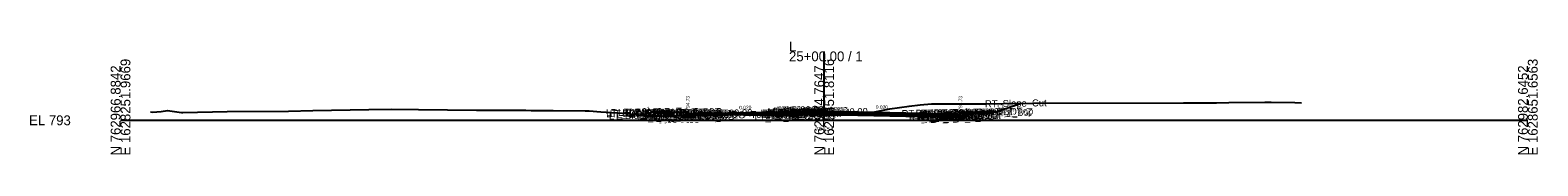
# Model space of a CAD drawing. Extents: x -26 to 4403, y -510 to 9556.
# Drawn here: x 974.3 to 1402.8, y 4990.3 to 5022.4 of the extents above; entities that cross this region are included whole.
import ezdxf

# ---------------------------------------------------------------- set-up
doc = ezdxf.new("R2010")
doc.units = 0
for name, color, linetype in [('Default', 7, 'Continuous'), ('Exist CMT Pavement', 7, 'Continuous'), ('Exist Cross Section Cell', 7, 'Continuous'), ('Exist XS Center Line Elevation Label', 7, 'Continuous'), ('Exist XS Ground Line', 7, 'Continuous'), ('Prop CMT Conc Surface', 7, 'Continuous'), ('Prop CMT Concrete Structures', 7, 'Continuous'), ('Prop CMT Pvmt Course 1', 7, 'Continuous'), ('Prop CMT Pvmt Course 1 CG', 7, 'Continuous'), ('Prop CMT Pvmt Course 1 Wedge', 7, 'Continuous'), ('Prop CMT Pvmt Course 2', 7, 'Continuous'), ('Prop CMT Pvmt Course 2 Wedge', 7, 'Continuous'), ('Prop CMT Pvmt Course 3', 7, 'Continuous'), ('Prop CMT Pvmt Course 3 Wedge', 7, 'Continuous'), ('Prop CMT Pvmt Surface', 7, 'Continuous'), ('Prop CMT Pvmt Wedge Surface 1', 7, 'Continuous'), ('Prop CMT Pvmt Wedge Surface 2', 7, 'Continuous'), ('Prop CMT Pvmt Wedge Surface 3', 7, 'Continuous'), ('Prop CMT Slope Grass', 7, 'Continuous'), ('Prop CMT Subgrade Earthwork', 7, 'Continuous'), ('Prop XS Hydro Elevations', 7, 'Continuous'), ('Prop XS SE Text', 7, 'Continuous'), ('Prop XS Side Slope Text', 7, 'Continuous'), ('Scratch_Level_0', 7, 'Continuous')]:
    doc.layers.add(name, color=color, linetype=linetype)

msp = doc.modelspace()

# ---------------------------------------------------------------- linework, layer by layer
at = {"layer": 'Exist CMT Pavement'}
msp.add_lwpolyline([(1163.26, 5001.5), (1165.91, 5001.58), (1171.22, 5001.76), (1177.05, 5001.59), (1190.76, 5001.23)], dxfattribs=at)
at = {"layer": 'Exist Cross Section Cell'}
for p, q in [((1200, 5000), (1200, 5019.58)), ((1000, 5000), (1200, 5000)), ((1200, 5000), (1400, 5000))]:
    msp.add_line(p, q, dxfattribs=at)
at = {"layer": 'Exist XS Ground Line'}
msp.add_lwpolyline([(1008.56, 5002.39), (1009.11, 5002.29), (1011.55, 5002.52), (1013.37, 5002.75), (1017.29, 5002.23), (1017.69, 5002.25), (1030.33, 5002.55), (1047.76, 5002.63), (1054.68, 5002.75), (1070.56, 5003.07), (1077.15, 5003.2), (1084.67, 5003.08), (1101.19, 5002.84), (1115.16, 5002.84), (1116.75, 5002.83), (1122.95, 5002.79), (1132.03, 5002.72), (1133.23, 5002.74), (1136.5, 5002.42), (1144.19, 5001.94), (1149.29, 5001.32), (1149.78, 5001.1), (1165.91, 5001.58), (1171.22, 5001.76), (1177.05, 5001.59), (1190.72, 5001.23), (1191.91, 5001.1), (1193.24, 5001.54), (1195.22, 5001.7), (1198.62, 5001.58), (1199.18, 5001.54), (1200, 5001.54), (1204.18, 5001.54), (1204.52, 5001.51), (1204.87, 5001.54), (1210.64, 5001.56), (1214.42, 5002.42), (1218.67, 5003.25), (1224.14, 5004.06), (1227.27, 5004.38), (1230.51, 5004.67), (1235.17, 5004.7), (1245.87, 5004.68), (1250.96, 5004.81), (1259.59, 5004.9), (1302.16, 5005.01), (1311.53, 5004.94), (1315.05, 5005.02), (1325.23, 5005.19), (1327.02, 5005.16), (1333.74, 5005.07), (1335.68, 5005)], dxfattribs=at)
at = {"layer": 'Prop CMT Conc Surface'}
for points in [[(1156.75, 5002.32), (1151.75, 5002.42)], [(1161.25, 5001.73), (1161.25, 5002.23), (1160.75, 5002.23)], [(1163.25, 5001.85), (1161.25, 5001.73)], [(1236.75, 5001.85), (1238.75, 5001.73)], [(1238.75, 5001.73), (1238.75, 5002.23), (1239.25, 5002.23)], [(1243.25, 5002.32), (1248.25, 5002.42)]]:
    msp.add_lwpolyline(points, dxfattribs=at)
at = {"layer": 'Prop CMT Concrete Structures'}
for points in [[(1151.75, 5002.09), (1151.75, 5002.42)], [(1151.75, 5002.42), (1156.75, 5002.32)], [(1156.75, 5001.99), (1151.75, 5002.09)], [(1156.75, 5002.32), (1156.75, 5001.99)], [(1163.25, 5001.85), (1161.25, 5001.73), (1161.25, 5002.23), (1160.75, 5002.23)], [(1160.75, 5002.23), (1160.75, 5001.22), (1163.25, 5001.27)], [(1163.25, 5001.27), (1163.25, 5001.85)], [(1196, 5002.67), (1195.99, 5002.83), (1195.24, 5003.08), (1194, 5003.11), (1192.76, 5002.84), (1192.01, 5002.59), (1192, 5002.43)], [(1192, 5002.43), (1196, 5002.67)], [(1236.75, 5001.85), (1238.75, 5001.73), (1238.75, 5002.23), (1239.25, 5002.23)], [(1239.25, 5002.23), (1239.25, 5001.22), (1236.75, 5001.27)], [(1236.75, 5001.27), (1236.75, 5001.85)], [(1248.25, 5002.42), (1243.25, 5002.32)], [(1243.25, 5002.32), (1243.25, 5001.99)], [(1243.25, 5001.99), (1248.25, 5002.09)], [(1248.25, 5002.09), (1248.25, 5002.42)]]:
    msp.add_lwpolyline(points, dxfattribs=at)
at = {"layer": 'Prop CMT Pvmt Course 1'}
for points in [[(1192, 5002.43), (1163.25, 5001.85)], [(1163.25, 5001.73), (1192, 5002.3)], [(1163.25, 5001.85), (1163.25, 5001.6), (1163.25, 5001.6), (1163.25, 5001.73)], [(1192, 5002.43), (1196, 5002.67)], [(1192, 5002.18), (1192, 5002.43)], [(1192, 5002.18), (1192, 5002.43)], [(1196, 5002.42), (1192, 5002.18)], [(1192, 5002.3), (1192, 5002.18), (1192, 5002.18)], [(1196, 5002.67), (1196, 5002.42)], [(1196, 5002.67), (1236.75, 5001.85)], [(1196, 5002.42), (1196, 5002.67)], [(1236.75, 5001.6), (1196, 5002.42)], [(1236.75, 5001.85), (1236.75, 5001.6)]]:
    msp.add_lwpolyline(points, dxfattribs=at)
msp.add_lwpolyline([(1196, 5002.42), (1196, 5002.54), (1196, 5002.54), (1196, 5002.42)], close=True, dxfattribs=at)
at = {"layer": 'Prop CMT Pvmt Course 1 CG'}
for points in [[(1163.25, 5001.27), (1160.25, 5001.21), (1159.91, 5000.87)], [(1163.25, 5000.94), (1163.25, 5001.27)], [(1236.75, 5001.27), (1239.75, 5001.21), (1240.09, 5000.87)], [(1236.75, 5000.94), (1236.75, 5001.27)], [(1159.91, 5000.87), (1163.25, 5000.94)], [(1240.09, 5000.87), (1236.75, 5000.94)]]:
    msp.add_lwpolyline(points, dxfattribs=at)
at = {"layer": 'Prop CMT Pvmt Course 1 Wedge'}
for points in [[(1163.25, 5001.73), (1165.91, 5001.78), (1171.22, 5001.89), (1171.27, 5001.89), (1177.05, 5002), (1190.72, 5002.28), (1191.66, 5002.3), (1191.91, 5002.3), (1192, 5002.3)], [(1192, 5002.18), (1191.91, 5002.18), (1191.66, 5002.17), (1190.72, 5002.15), (1177.05, 5001.88), (1171.27, 5001.76), (1171.22, 5001.76), (1165.91, 5001.66), (1163.25, 5001.6)], [(1163.25, 5001.6), (1163.25, 5001.73)], [(1192, 5002.3), (1192, 5002.18)]]:
    msp.add_lwpolyline(points, dxfattribs=at)
at = {"layer": 'Prop CMT Pvmt Course 2'}
for points in [[(1163.25, 5001.27), (1163.25, 5001.27), (1163.25, 5001.6), (1163.25, 5001.6)], [(1163.25, 5001.6), (1163.25, 5001.27)], [(1192, 5002.18), (1196, 5002.42)], [(1192, 5001.84), (1192, 5002.18)], [(1196, 5002.08), (1192, 5001.84)], [(1196, 5002.42), (1196, 5002.08)], [(1196, 5002.08), (1196, 5002.42)], [(1196, 5002.42), (1236.75, 5001.6)], [(1236.75, 5001.27), (1196, 5002.08)], [(1236.75, 5001.6), (1236.75, 5001.27)]]:
    msp.add_lwpolyline(points, dxfattribs=at)
at = {"layer": 'Prop CMT Pvmt Course 2 Wedge'}
for points in [[(1163.25, 5001.6), (1165.91, 5001.66), (1171.22, 5001.76), (1171.27, 5001.76), (1177.05, 5001.88), (1190.72, 5002.15), (1191.66, 5002.17), (1191.91, 5002.18), (1192, 5002.18)], [(1192, 5001.84), (1191.91, 5001.84), (1191.66, 5001.84), (1190.72, 5001.82), (1178.12, 5001.57), (1177.05, 5001.59), (1171.27, 5001.75), (1171.22, 5001.76), (1165.91, 5001.58), (1163.25, 5001.5)], [(1163.25, 5001.5), (1163.25, 5001.6)], [(1192, 5002.18), (1192, 5001.84)]]:
    msp.add_lwpolyline(points, dxfattribs=at)
at = {"layer": 'Prop CMT Pvmt Course 3'}
for points in [[(1163.25, 5001.27), (1163.25, 5001.27), (1163.25, 5000.94), (1163.25, 5000.94)], [(1163.25, 5000.94), (1163.25, 5001.27)], [(1192, 5001.84), (1196, 5002.08)], [(1192, 5001.51), (1192, 5001.84)], [(1196, 5001.75), (1192, 5001.51)], [(1196, 5002.08), (1196, 5001.75)], [(1196, 5002.08), (1236.75, 5001.27)], [(1196, 5001.75), (1196, 5002.08)], [(1236.75, 5000.94), (1196, 5001.75)], [(1236.75, 5001.27), (1236.75, 5000.94)]]:
    msp.add_lwpolyline(points, dxfattribs=at)
at = {"layer": 'Prop CMT Pvmt Course 3 Wedge'}
for points in [[(1178.12, 5001.57), (1190.72, 5001.82)], [(1192, 5001.14), (1191.91, 5001.1), (1191.66, 5001.12), (1190.72, 5001.23), (1178.12, 5001.57)], [(1190.72, 5001.82), (1191.66, 5001.84), (1191.91, 5001.84), (1192, 5001.84)]]:
    msp.add_lwpolyline(points, dxfattribs=at)
at = {"layer": 'Prop CMT Pvmt Surface'}
for points in [[(1192, 5002.43), (1163.25, 5001.85)], [(1192, 5002.43), (1196, 5002.67)], [(1196, 5002.67), (1236.75, 5001.85)]]:
    msp.add_lwpolyline(points, dxfattribs=at)
at = {"layer": 'Prop CMT Pvmt Wedge Surface 1'}
for points in [[(1192, 5002.3), (1163.25, 5001.73)], [(1163.25, 5001.6), (1163.25, 5001.85)], [(1163.25, 5001.73), (1163.25, 5001.6), (1163.25, 5001.6)], [(1192, 5002.43), (1192, 5002.18), (1192, 5002.18), (1192, 5002.3)]]:
    msp.add_lwpolyline(points, dxfattribs=at)
at = {"layer": 'Prop CMT Pvmt Wedge Surface 2'}
for points in [[(1192, 5002.18), (1163.25, 5001.6)], [(1163.25, 5001.6), (1163.25, 5001.85)], [(1192, 5002.43), (1192, 5002.18)]]:
    msp.add_lwpolyline(points, dxfattribs=at)
at = {"layer": 'Prop CMT Pvmt Wedge Surface 3'}
for points in [[(1163.25, 5001.27), (1163.25, 5001.85)], [(1192, 5001.84), (1163.25, 5001.27)], [(1192, 5002.43), (1192, 5001.84)]]:
    msp.add_lwpolyline(points, dxfattribs=at)
at = {"layer": 'Prop CMT Slope Grass'}
for points in [[(1160.75, 5002.23), (1151.25, 5002.42), (1148.31, 5001.44)], [(1239.25, 5002.23), (1248.25, 5002.41)], [(1248.25, 5002.41), (1248.75, 5002.42), (1256.08, 5004.87)]]:
    msp.add_lwpolyline(points, dxfattribs=at)
at = {"layer": 'Prop CMT Subgrade Earthwork'}
for points in [[(1163.25, 5000.94), (1159.91, 5000.87), (1158.5, 5002.28)], [(1163.25, 5000.94), (1163.26, 5001.5)], [(1190.76, 5001.49), (1191.66, 5001.5), (1191.91, 5001.51), (1192, 5001.51)], [(1190.76, 5001.49), (1190.76, 5001.22)], [(1192, 5001.51), (1196, 5001.75)], [(1196, 5001.75), (1236.75, 5000.94)], [(1236.75, 5000.94), (1240.09, 5000.87), (1241.5, 5002.28)], [(1163.25, 5000.94), (1163.25, 5000.94)]]:
    msp.add_lwpolyline(points, dxfattribs=at)

# ---------------------------------------------------------------- texts
at = {"layer": 'Default'}
msp.add_text('-', height=0.0001, dxfattribs=at).set_placement((1000, 5000))
at = {"layer": 'Exist Cross Section Cell'}
for s, p in [('25+00.00 / 1', (1190, 5016.78)), ('L', (1190, 5019.58)), ('EL 793', (974, 4998.6))]:
    msp.add_text(s, height=2.8, dxfattribs=at).set_placement(p)
for s, p in [('N 762966.8842', (1000, 4990)), ('E 1628251.9669', (1002.8, 4990)), ('N 762974.7647', (1200, 4990)), ('E 1628451.8116', (1202.8, 4990)), ('N 762982.6452', (1400, 4990)), ('E 1628651.6563', (1402.8, 4990))]:
    msp.add_text(s, height=2.8, rotation=90, dxfattribs=at).set_placement(p)
at = {"layer": 'Exist XS Center Line Elevation Label'}
msp.add_text('794.54', height=1.2, dxfattribs=at).set_placement((1197.5, 4996.94))
at = {"layer": 'Prop XS Hydro Elevations'}
for p in [(1161.75, 5002.73), (1239.25, 5002.73)]:
    msp.add_text('794.73', height=1, rotation=90, dxfattribs=at).set_placement(p)
at = {"layer": 'Prop XS SE Text'}
for rotation, p in [(1.1457, (1175.86, 5003.1)), (358.8542, (1214.65, 5003.29))]:
    msp.add_text('0.020', height=1, rotation=rotation, dxfattribs=at).set_placement(p)
at = {"layer": 'Prop XS Side Slope Text'}
for rotation, p in [(18.4391, (1148.79, 5002.39)), (18.4332, (1249.3, 5003.15))]:
    msp.add_text('3:1', height=1, rotation=rotation, dxfattribs=at).set_placement(p)
at = {"layer": 'Scratch_Level_0'}
for s, p in [('RT_Slope_Cut', (1245.7, 5003.66)), ('LT_SDWK_Out_Top', (1138.01, 5001.15)), ('LT_SDWK_Out_Bot', (1138.04, 5000.81)), ('LT_Slope_Fill', (1138.85, 5000.25)), ('LT_Sub_Trench_Out_DLT', (1139.09, 5000.89)), ('LT_CSLP_Pnt', (1141.44, 5001.23)), ('LT_SDWK_In_Top', (1144.63, 5001.08)), ('LT_SDWK_In_Bot', (1144.66, 5000.75)), ('LT_CG1_Shelf_Out', (1146.82, 4999.94)), ('LT_PV_Sub_Tie_Out', (1148.23, 5000.2)), ('LT_CG_Top_Face', (1148.53, 5000.98)), ('LT_CG_Top_BOC', (1149.05, 5001)), ('LT_CG_Bot_BOC', (1149.09, 4999.99)), ('LT_CG_Top_Gut', (1149.51, 5000.5)), ('LT_Sub_OEOP', (1150.04, 4999.67)), ('LT_Sub_OEOT_CG', (1150.64, 4999.68)), ('LT_PV_OEEOP_EG', (1150.82, 5000.25)), ('LT_Sub_OEEOP', (1152.48, 4999.72)), ('LT_PV2_OEEOP', (1152.58, 5000.39)), ('LT_PV3_OEEOP', (1152.58, 5000.06)), ('LT_PV1_OEEOP', (1153.15, 5000.52)), ('LT_CG_Bot_IE', (1153.19, 5000.07)), ('LT_Sub_OEOT', (1153.35, 4999.74)), ('25+00.00', (1153.51, 5001.1)), ('LT_PV2_OEOT', (1153.45, 5000.41)), ('LT_PV3_OEOT', (1153.45, 5000.07)), ('LT_PV1_OEOT', (1154.01, 5000.67)), ('25+00.00', (1154.13, 5001.1)), ('LT_PV_EG_TestPt', (1164.06, 5000.31)), ('25+00.00', (1168.39, 5000.95)), ('LT_PV_IEEOP_EG', (1180.21, 4999.91)), ('LT_PV2_IEEOP', (1181.97, 5000.98)), ('LT_PV3_IEEOP', (1181.97, 5000.64)), ('LT_PV1_IEEOP', (1182.54, 5001.11)), ('LT_PV2_PGL1', (1182.9, 5000.99)), ('LT_PV3_PGL1', (1182.9, 5000.66)), ('LT_PV2_PGL', (1183.23, 5001)), ('LT_PV3_PGL', (1183.23, 5000.67)), ('LT_PV4_PGL', (1183.23, 5000.33)), ('LT_PV1_PGL', (1183.8, 5001.26)), ('MI_Face In', (1183.92, 5001.43)), ('25+00.00', (1185.2, 5001.43)), ('RT_Sub_OEEOP', (1185.19, 5000.53)), ('RT_PV2_OEEOP', (1185.28, 5001.2)), ('RT_PV3_OEEOP', (1185.28, 5000.87)), ('25+00.00', (1185.36, 5001.51)), ('MI_Top In', (1185.63, 5001.7)), ('RT_PV1_OEEOP', (1185.85, 5001.34)), ('RT_PV2_IEEOP', (1185.93, 5001.22)), ('MI_Face Out', (1186.28, 5001.64)), ('MI_Top Out', (1186.49, 5001.91)), ('RT_PV1_IEEOP', (1186.49, 5001.35)), ('RT_PV2_PGL1', (1186.86, 5001.23)), ('RT_PV3_PGL1', (1186.86, 5000.9)), ('MI_Crown', (1187.09, 5001.97)), ('RT_PV2_PGL', (1187.19, 5001.24)), ('RT_PV4_PGL', (1187.19, 5000.57)), ('MI_Bot Out', (1187.28, 5001.49)), ('RT_PV1_PGL', (1187.75, 5001.5)), ('25+00.00', (1188.67, 5001.87)), ('25+00.00', (1189.18, 5001.57)), ('25+00.00', (1201.19, 5001.29)), ('RT_Sub_Trench_Out_DLT', (1222.04, 5000.89)), ('RT_Sub_OEOT_CG', (1224.1, 4999.68)), ('RT_CG_Top_Face', (1225.99, 5000.98)), ('RT_CG1_Shelf_Out', (1226.28, 4999.94)), ('RT_CG_Bot_IE', (1226.64, 5000.07)), ('RT_Sub_OEOT', (1226.8, 4999.74)), ('RT_PV2_OEOT', (1226.9, 5000.4)), ('RT_PV3_OEOT', (1226.9, 5000.07)), ('RT_CG_Top_Gut', (1226.96, 5000.5)), ('RT_PV1_OEOT', (1227.46, 5000.67)), ('RT_CG_Top_BOC', (1227.51, 5001)), ('RT_CG_Bot_BOC', (1227.54, 4999.98)), ('RT_Sub_OEOP', (1230.18, 4999.67)), ('RT_SDWK_In_Top', (1231.08, 5001.08)), ('RT_SDWK_In_Bot', (1231.11, 5000.75)), ('25+00.00', (1232.22, 5001.1)), ('25+00.00', (1233.96, 5001.13)), ('RT_SDWK_Out_Top', (1234.46, 5001.15)), ('RT_SDWK_Out_Bot', (1234.49, 5000.81)), ('RT_Shld_O', (1240.81, 5001.26)), ('CSLP_Pnt', (1241.64, 5001.28))]:
    msp.add_text(s, height=2, rotation=1.1458, dxfattribs=at).set_placement(p)

doc.saveas('drawing.dxf')
